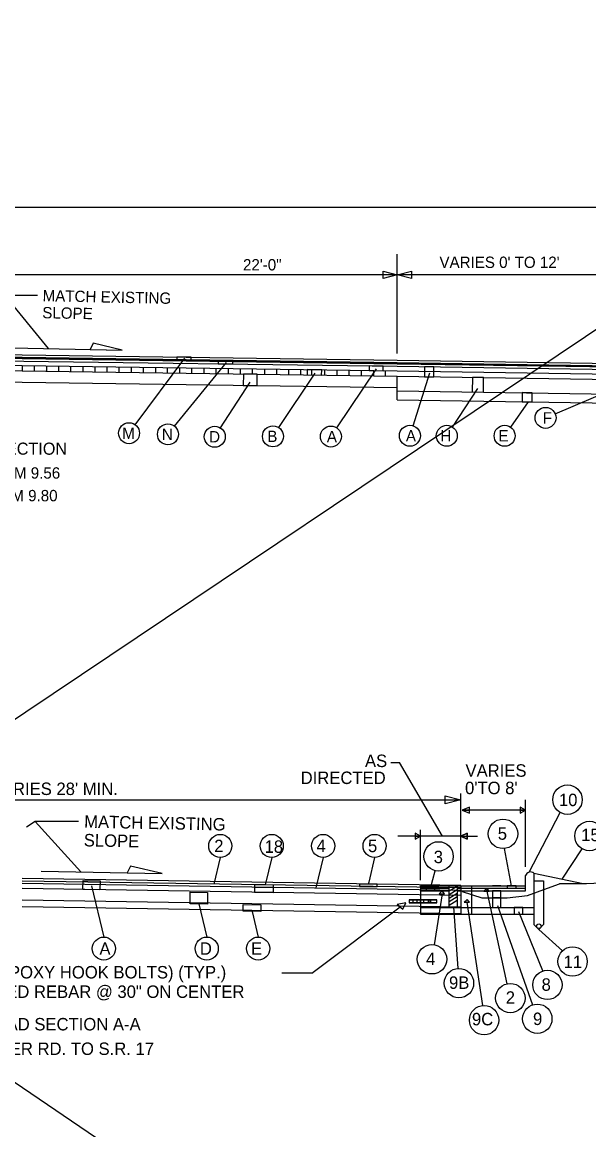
# Model space of a CAD drawing. Extents: x 227 to 993, y -530 to -180.
# Drawn here: x 395.8 to 430.2, y -485.8 to -418.6 of the extents above; entities that cross this region are included whole.
import ezdxf

# ---------------------------------------------------------------- set-up
doc = ezdxf.new("R2010")
doc.units = 0
for name, color, linetype in [('Default', 7, 'Continuous'), ('Level 1', 7, 'Continuous'), ('Level 10', 7, 'Continuous'), ('Level 11', 7, 'Continuous'), ('Level 40', 7, 'Continuous'), ('Level 59', 7, 'Continuous')]:
    doc.layers.add(name, color=color, linetype=linetype)

msp = doc.modelspace()

# ---------------------------------------------------------------- linework, layer by layer
at = {"layer": 'Default'}
for p, q in [((418.171, -463.537), (418.69, -463.537)), ((421.307, -468.009), (418.69, -463.537)), ((426.343, -469.853), (426.343, -465.793)), ((426.343, -466.433), (422.501, -466.433)), ((426.343, -466.433), (426.011, -466.254)), ((426.011, -466.254), (426.011, -466.599)), ((426.011, -466.599), (426.343, -466.433)), ((426.553, -470.184), (428.447, -466.569)), ((419.973, -468.009), (418.59, -468.009)), ((419.642, -467.83), (419.642, -468.176)), ((419.642, -468.176), (419.973, -468.009)), ((419.973, -468.009), (419.642, -468.009)), ((419.642, -468.009), (419.642, -468.176)), ((419.642, -468.009), (419.973, -468.009)), ((419.642, -468.176), (419.973, -468.009)), ((419.973, -470.677), (419.973, -467.62)), ((422.406, -468.009), (419.973, -468.009)), ((422.406, -468.009), (422.792, -467.83)), ((422.792, -468.176), (422.406, -468.009)), ((422.406, -468.009), (423.418, -468.009)), ((422.792, -467.83), (422.792, -468.176)), ((425.489, -471.015), (425.059, -468.748)), ((428.568, -470.604), (429.77, -468.762)), ((420.572, -471.166), (420.855, -470.097)), ((426.838, -470.243), (426.838, -473.356)), ((426.838, -470.243), (429.84, -470.869)), ((416.793, -470.905), (416.262, -470.905)), ((416.262, -470.905), (416.262, -471.048)), ((416.819, -470.793), (416.793, -470.905)), ((417.328, -470.913), (416.793, -470.905)), ((417.328, -471.048), (417.328, -470.913)), ((426.343, -471.318), (426.343, -470.398)), ((426.85, -470.706), (427.419, -470.706)), ((427.419, -470.706), (427.419, -473.356)), ((410.537, -470.958), (409.9, -470.958)), ((409.9, -470.958), (409.9, -471.099)), ((409.9, -471.099), (411.044, -471.099)), ((411.044, -470.966), (410.537, -470.958)), ((411.044, -471.099), (411.044, -470.966)), ((416.262, -471.048), (417.328, -471.048)), ((419.964, -471.076), (419.964, -471.019)), ((419.964, -471.076), (419.964, -472.729)), ((419.973, -471.015), (426.343, -471.015)), ((419.973, -471.166), (421.699, -471.166)), ((419.973, -471.318), (421.699, -471.318)), ((420.3, -471.166), (420.3, -471.318)), ((420.838, -471.166), (420.3, -471.166)), ((420.3, -471.166), (420.572, -471.166)), ((420.3, -471.318), (420.838, -471.318)), ((421.271, -471.493), (420.786, -474.586)), ((420.838, -471.318), (420.838, -471.166)), ((421.278, -471.316), (421.094, -471.493)), ((421.094, -471.493), (421.417, -471.493)), ((421.417, -471.493), (421.278, -471.316)), ((421.699, -471.042), (421.699, -471.015)), ((421.699, -472.326), (421.699, -471.042)), ((422.194, -471.05), (421.699, -471.345)), ((422.194, -471.264), (421.699, -471.559)), ((422.194, -471.481), (421.699, -471.776)), ((422.194, -471.05), (422.194, -471.015)), ((422.194, -471.05), (422.194, -472.3)), ((422.194, -471.166), (426.343, -471.166)), ((422.194, -471.318), (426.343, -471.318)), ((423.984, -471.165), (423.8, -471.342)), ((423.8, -471.342), (424.124, -471.342)), ((423.976, -471.26), (425.21, -476.954)), ((424.124, -471.342), (423.984, -471.165)), ((424.837, -471.015), (424.334, -471.015)), ((425.224, -471.015), (425.224, -471.166)), ((425.764, -471.015), (425.224, -471.015)), ((425.224, -471.166), (425.764, -471.166)), ((425.764, -471.166), (425.764, -471.015)), ((419.065, -472.037), (418.543, -472.145)), ((418.722, -472.295), (418.543, -472.145)), ((418.543, -472.145), (418.883, -472.43)), ((418.883, -472.43), (419.065, -472.037)), ((419.271, -471.867), (420.955, -471.867)), ((420.955, -472.037), (419.271, -472.037)), ((419.973, -471.868), (419.973, -472.039)), ((419.973, -472.039), (419.973, -471.868)), ((419.973, -472.039), (420.164, -472.039)), ((420.955, -472.037), (420.018, -472.037)), ((420.581, -472.037), (420.13, -472.037)), ((420.138, -471.867), (420.581, -471.867)), ((420.581, -471.867), (420.581, -472.037)), ((422.194, -471.688), (421.699, -471.983)), ((422.194, -471.91), (421.699, -472.205)), ((422.802, -471.834), (422.618, -472.011)), ((422.785, -472.011), (422.618, -472.011)), ((422.618, -472.011), (422.942, -472.011)), ((422.942, -472.011), (422.802, -471.834)), ((423.745, -478.274), (422.804, -472.011)), ((424.837, -471.745), (424.334, -471.745)), ((424.334, -471.745), (424.837, -471.745)), ((424.646, -472.215), (426.759, -478.236)), ((413.365, -476.317), (418.722, -472.295)), ((419.964, -472.729), (426.838, -472.729)), ((419.973, -472.326), (426.838, -472.326)), ((421.967, -472.297), (422.238, -476.026)), ((424.334, -472.326), (424.837, -472.326)), ((426.172, -472.326), (425.649, -472.326)), ((425.649, -472.326), (425.649, -472.729)), ((425.649, -472.729), (426.172, -472.729)), ((427.397, -476.172), (425.935, -472.584)), ((426.172, -472.729), (426.172, -472.326)), ((427.145, -473.671), (426.838, -473.356)), ((427.419, -473.356), (427.145, -473.671)), ((427.145, -473.671), (428.579, -474.955)), ((413.365, -476.317), (411.559, -476.317))]:
    msp.add_line(p, q, dxfattribs=at)
for points in [[(422.501, -466.433), (422.939, -466.433), (422.939, -466.254), (422.501, -466.433)], [(422.939, -466.433), (422.501, -466.433), (422.939, -466.599), (422.939, -466.433)], [(426.011, -466.433), (426.343, -466.433), (426.011, -466.254), (426.011, -466.433)], [(426.011, -466.599), (426.343, -466.433), (426.011, -466.433), (426.011, -466.599)], [(419.973, -468.009), (419.642, -467.83), (419.642, -468.009)], [(421.417, -471.493), (421.278, -471.316), (421.094, -471.493), (421.417, -471.493)], [(424.124, -471.342), (423.984, -471.165), (423.8, -471.342), (424.124, -471.342)], [(424.837, -471.745), (424.837, -471.318), (424.334, -471.318), (424.334, -471.745)], [(419.772, -471.867), (419.271, -471.867), (419.271, -472.037), (419.772, -472.037), (419.772, -471.867)], [(419.973, -471.868), (419.503, -471.868), (419.503, -472.039), (419.973, -472.039)], [(420.164, -472.039), (420.164, -471.868), (419.973, -471.868)], [(420.556, -471.867), (420.138, -471.867), (420.138, -472.037), (420.556, -472.037), (420.556, -471.867)], [(420.955, -471.867), (420.434, -471.867), (420.434, -472.037), (420.955, -472.037), (420.955, -471.867)], [(422.942, -472.011), (422.802, -471.834), (422.618, -472.011), (422.942, -472.011)], [(424.334, -471.745), (424.334, -472.326), (424.837, -472.326), (424.837, -471.745)]]:
    msp.add_lwpolyline(points, dxfattribs=at)
for points in [[(422.792, -467.83), (422.406, -468.009), (422.792, -468.176)], [(417.328, -470.913), (416.793, -470.905), (416.262, -470.905), (416.262, -471.048), (417.328, -471.048)], [(411.049, -470.966), (409.892, -470.948), (409.885, -471.4), (411.042, -471.418)], [(411.044, -470.966), (410.537, -470.958), (409.9, -470.958), (409.9, -471.099), (411.044, -471.099)], [(420.838, -471.166), (420.3, -471.166), (420.3, -471.318), (420.838, -471.318)], [(425.764, -471.015), (425.224, -471.015), (425.224, -471.166), (425.764, -471.166)], [(419.065, -472.037), (418.543, -472.145), (418.883, -472.43)], [(425.649, -472.729), (426.172, -472.729), (426.172, -472.326), (425.649, -472.326)]]:
    msp.add_lwpolyline(points, close=True, dxfattribs=at)
for centre, radius in [((428.883, -465.79), 0.892), ((424.969, -467.86), 0.892), ((430.22, -467.992), 0.892), ((421.06, -469.229), 0.892), ((427.147, -473.465), 0.136), ((420.662, -475.47), 0.892), ((429.192, -475.604), 0.892), ((422.297, -476.916), 0.892), ((427.666, -477.023), 0.892), ((425.416, -477.823), 0.892), ((423.824, -479.163), 0.892), ((427.052, -479.078), 0.892)]:
    msp.add_circle(centre, radius, dxfattribs=at)
msp.add_arc((426.64, -470.48), 0.308, 49.98753, 164.59484, dxfattribs=at)
at = {"layer": 'Level 1'}
for p, q in [((316.833, -429.85), (442.833, -429.85)), ((427.676, -471.161), (428.392, -470.901)), ((430.043, -470.901), (428.392, -470.901)), ((431.349, -470.839), (430.043, -470.901)), ((422.501, -471.357), (423.692, -471.745)), ((423.052, -471.053), (423.052, -472.728)), ((425.232, -471.745), (426.467, -471.599)), ((426.467, -471.599), (427.676, -471.161)), ((419.271, -472.037), (420.955, -472.037)), ((420.955, -471.867), (420.343, -471.867)), ((423.692, -471.745), (425.232, -471.745))]:
    msp.add_line(p, q, dxfattribs=at)
at = {"layer": 'Level 11'}
for p, q in [((300.629, -418.634), (464.796, -530.075)), ((292.845, -529.603), (457.012, -419.578)), ((394.731, -435.22), (397.37, -438.424)), ((396.727, -435.22), (394.731, -435.22)), ((394.352, -438.796), (418.552, -439.136)), ((394.352, -439.002), (418.552, -439.343)), ((394.352, -439.012), (418.552, -439.352)), ((394.352, -439.165), (418.552, -439.506)), ((394.353, -438.933), (418.553, -439.274)), ((394.355, -438.796), (418.555, -439.136)), ((418.552, -439.136), (431.855, -439.335)), ((418.552, -439.343), (431.881, -439.542)), ((418.552, -439.352), (431.879, -439.551)), ((418.553, -439.274), (431.892, -439.473)), ((418.555, -439.136), (431.915, -439.336)), ((394.352, -439.445), (418.552, -439.785)), ((394.352, -439.77), (418.552, -440.11)), ((395.815, -439.79), (395.815, -439.465)), ((396.542, -439.8), (396.542, -439.475)), ((397.284, -439.811), (397.284, -439.486)), ((398.015, -439.821), (398.015, -439.496)), ((398.752, -439.832), (398.752, -439.507)), ((399.494, -439.842), (399.494, -439.517)), ((400.215, -439.852), (400.215, -439.527)), ((400.947, -439.862), (400.947, -439.537)), ((401.683, -439.873), (401.683, -439.548)), ((402.42, -439.883), (402.42, -439.558)), ((403.152, -439.893), (403.152, -439.569)), ((403.899, -439.904), (403.899, -439.579)), ((404.62, -439.914), (404.62, -439.589)), ((405.352, -439.924), (405.352, -439.599)), ((406.098, -439.935), (406.098, -439.61)), ((406.83, -439.945), (406.83, -439.62)), ((407.567, -439.956), (407.567, -439.631)), ((408.304, -439.966), (408.304, -439.641)), ((409.035, -439.976), (409.035, -439.651)), ((409.772, -439.987), (409.772, -439.662)), ((410.509, -439.997), (410.509, -439.672)), ((411.246, -440.007), (411.246, -439.682)), ((411.972, -440.018), (411.972, -439.693)), ((412.709, -440.028), (412.709, -439.703)), ((413.363, -440.037), (413.363, -439.712)), ((414.151, -440.048), (414.151, -439.723)), ((414.903, -440.059), (414.903, -439.734)), ((415.64, -440.069), (415.64, -439.744)), ((416.392, -440.08), (416.392, -439.755)), ((417.124, -440.09), (417.124, -439.765)), ((417.85, -440.1), (417.85, -439.775)), ((418.552, -439.506), (431.855, -439.704)), ((418.552, -439.785), (431.855, -439.984)), ((394.352, -440.452), (418.552, -440.793)), ((418.552, -441.546), (418.552, -440.11)), ((418.552, -440.11), (431.855, -440.309)), ((418.552, -440.99), (431.645, -441.186)), ((418.552, -441.546), (431.855, -441.745)), ((422.406, -470.676), (422.406, -465.419)), ((369.166, -465.796), (422.406, -465.796)), ((396.587, -467.111), (396.06, -467.458)), ((399.211, -467.111), (396.587, -467.111)), ((396.587, -467.111), (399.358, -470.173)), ((422.416, -470.993), (395.796, -470.576)), ((422.416, -471.144), (395.796, -470.727)), ((422.416, -471.295), (395.796, -470.878)), ((422.416, -471.598), (395.796, -471.181)), ((422.416, -470.993), (422.416, -472.707)), ((422.416, -470.993), (422.416, -471.144)), ((422.416, -472.304), (395.796, -471.887)), ((422.416, -472.707), (395.796, -472.29))]:
    msp.add_line(p, q, dxfattribs=at)
for points in [[(420.197, -440.135), (420.772, -440.143), (420.781, -439.539), (420.206, -439.53)], [(423.1, -441.058), (423.781, -441.068), (423.794, -440.188), (423.113, -440.178)], [(426.13, -441.659), (426.736, -441.668), (426.744, -441.113), (426.138, -441.104)], [(421.464, -465.561), (422.406, -465.796), (421.464, -466.032)]]:
    msp.add_lwpolyline(points, close=True, dxfattribs=at)
for centre, radius in [((427.554, -442.634), 0.636), ((402.277, -443.564), 0.636), ((404.64, -443.632), 0.636), ((407.48, -443.778), 0.636), ((411.012, -443.754), 0.636), ((414.525, -443.765), 0.636), ((419.321, -443.717), 0.636), ((421.56, -443.72), 0.636), ((425.071, -443.721), 0.636), ((400.748, -474.821), 0.7), ((406.991, -474.821), 0.7), ((410.113, -474.821), 0.7)]:
    msp.add_circle(centre, radius, dxfattribs=at)
at = {"layer": 'Level 40'}
for p, q in [((395.184, -438.379), (401.853, -438.518)), ((396.953, -470.123), (404.289, -470.276))]:
    msp.add_line(p, q, dxfattribs=at)
for points in [[(401.853, -438.518), (400.104, -438.102), (399.912, -438.477)], [(404.289, -470.276), (402.365, -469.818), (402.154, -470.231)]]:
    msp.add_lwpolyline(points, close=True, dxfattribs=at)
at = {"layer": 'Level 59'}
for p, q in [((418.552, -438.732), (418.552, -432.711)), ((418.552, -433.959), (394.352, -433.959)), ((431.848, -433.959), (418.552, -433.959)), ((431.848, -433.959), (418.552, -433.959)), ((402.658, -443.054), (405.669, -439.017)), ((405.043, -443.139), (408.194, -439.285)), ((411.366, -443.225), (413.574, -439.917)), ((414.881, -443.238), (417.298, -439.664)), ((419.513, -443.111), (420.528, -439.909)), ((407.827, -443.245), (409.63, -440.469)), ((421.91, -443.189), (423.447, -440.856)), ((428.14, -442.384), (431.943, -440.761)), ((425.438, -443.201), (426.522, -441.665)), ((407.814, -469.294), (407.427, -470.909)), ((410.936, -469.294), (410.537, -470.958)), ((414.057, -469.294), (413.613, -471.146)), ((417.179, -469.294), (416.819, -470.793)), ((400.002, -471.005), (400.748, -474.121)), ((406.511, -472.115), (406.991, -474.121)), ((409.741, -472.569), (410.113, -474.121))]:
    msp.add_line(p, q, dxfattribs=at)
for points in [[(417.696, -433.745), (418.552, -433.959), (417.696, -434.173)], [(419.409, -434.173), (418.552, -433.959), (419.409, -433.745)], [(405.181, -439.164), (406.045, -439.176), (406.048, -438.96), (405.184, -438.948)], [(407.69, -439.353), (408.57, -439.365), (408.572, -439.212), (407.692, -439.199)], [(409.204, -440.661), (410.046, -440.673), (410.056, -439.991), (409.214, -439.979)], [(413.086, -440.033), (413.964, -440.046), (413.968, -439.721), (413.09, -439.708)], [(416.841, -439.761), (417.689, -439.773), (417.693, -439.494), (416.845, -439.482)], [(399.49, -470.694), (400.524, -470.711), (400.514, -471.256), (399.48, -471.24)], [(405.995, -471.401), (407.049, -471.418), (407.038, -472.123), (405.984, -472.107)], [(409.212, -472.157), (410.283, -472.174), (410.276, -472.577), (409.206, -472.561)]]:
    msp.add_lwpolyline(points, close=True, dxfattribs=at)
for centre in [(407.814, -468.594), (410.936, -468.594), (414.057, -468.594), (417.179, -468.594)]:
    msp.add_circle(centre, 0.7, dxfattribs=at)

# ---------------------------------------------------------------- texts
at = {"layer": 'Default'}
for s, height, p in [('AS', 0.755, (416.595, -463.812)), ('DIRECTED ', 0.755, (412.691, -464.84)), ('VARIES', 0.755, (422.695, -464.399)), ("0'TO 8'", 0.755, (422.667, -465.455)), ('10', 0.755, (428.364, -466.18)), ('5', 0.755, (424.653, -468.219)), ('15', 0.755, (429.717, -468.305)), ('3', 0.755, (420.766, -469.639)), ('4', 0.755, (420.302, -475.819)), ('11', 0.755, (428.649, -475.997)), ('(OR 5/8" DIA. EPOXY HOOK BOLTS) (TYP.)', 0.75504, (387.901, -476.632)), ('9B', 0.755, (421.696, -477.264)), ('8', 0.755, (427.313, -477.379)), ('#5 EPOXY-COATED REBAR @ 30" ON CENTER', 0.75504, (386.802, -477.812)), ('2', 0.755, (425.138, -478.167)), ('9C', 0.755, (423.087, -479.476)), ('9', 0.755, (426.792, -479.458)), ('SHAAF RD./FUHRMEYER RD. TO S.R. 17', 0.75504, (384.384, -481.272))]:
    msp.add_text(s, height=height, dxfattribs=at).set_placement(p)
at = {"layer": 'Level 10'}
for s, height, p in [('NORMAL SECTION', 0.73333, (389.69, -444.868)), ('SLM 9.51 TO SLM 9.56', 0.6864, (388.458, -446.318)), ('SLM 9.59 TO SLM 9.80', 0.6864, (388.299, -447.691)), ('WEST CREEK ROAD SECTION A-A ', 0.75504, (386.378, -479.784))]:
    msp.add_text(s, height=height, dxfattribs=at).set_placement(p)
at = {"layer": 'Level 59'}
for s, height, p in [('22\'-0"', 0.6864, (409.194, -433.69)), ("VARIES 0' TO 12'", 0.6864, (421.115, -433.54)), ('F', 0.686, (427.387, -442.977)), ('M', 0.686, (401.866, -443.907)), ('N', 0.686, (404.27, -443.975)), ('A', 0.686, (419.078, -444.06)), ('H', 0.686, (421.171, -444.063)), ('E', 0.686, (424.695, -444.064)), ('D', 0.686, (407.14, -444.122)), ('B', 0.686, (410.669, -444.097)), ('A', 0.686, (414.281, -444.108)), ("VARIES 28' MIN.", 0.75504, (393.889, -465.507)), ('2', 0.755, (407.446, -468.971)), ('4', 0.755, (413.653, -468.971)), ('5', 0.755, (416.777, -468.971)), ('18', 0.755, (410.504, -469.014)), ('A', 0.755, (400.481, -475.198)), ('D', 0.755, (406.575, -475.198)), ('E', 0.755, (409.685, -475.198))]:
    msp.add_text(s, height=height, dxfattribs=at).set_placement(p)
for s, height, p in [('MATCH EXISTING', 0.6864, (397.029, -435.56)), ('SLOPE', 0.6864, (397.007, -436.59)), ('MATCH EXISTING', 0.75504, (399.548, -467.486)), ('SLOPE', 0.755, (399.524, -468.618))]:
    msp.add_text(s, height=height, rotation=358.80731, dxfattribs=at).set_placement(p)

doc.saveas('drawing.dxf')
